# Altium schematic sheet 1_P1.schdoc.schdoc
size 309 x 223 mm; Symbol: Sheet-Symbol_A4; Device: Sheet-Symbol_A4; @Page Name: P1; @Create Date: 2023-11-13; @Page Count: 1; @Page No: 1; @Project Name: circuller; @Schematic Name: Ver 2; @Update Date: 2023-11-14; Company: MPAM Laboratory; Drawed: FDS; Page Size: A4; Part Number: M-CIR-PCB-1; Reviewed: FDS; Version: V1.0
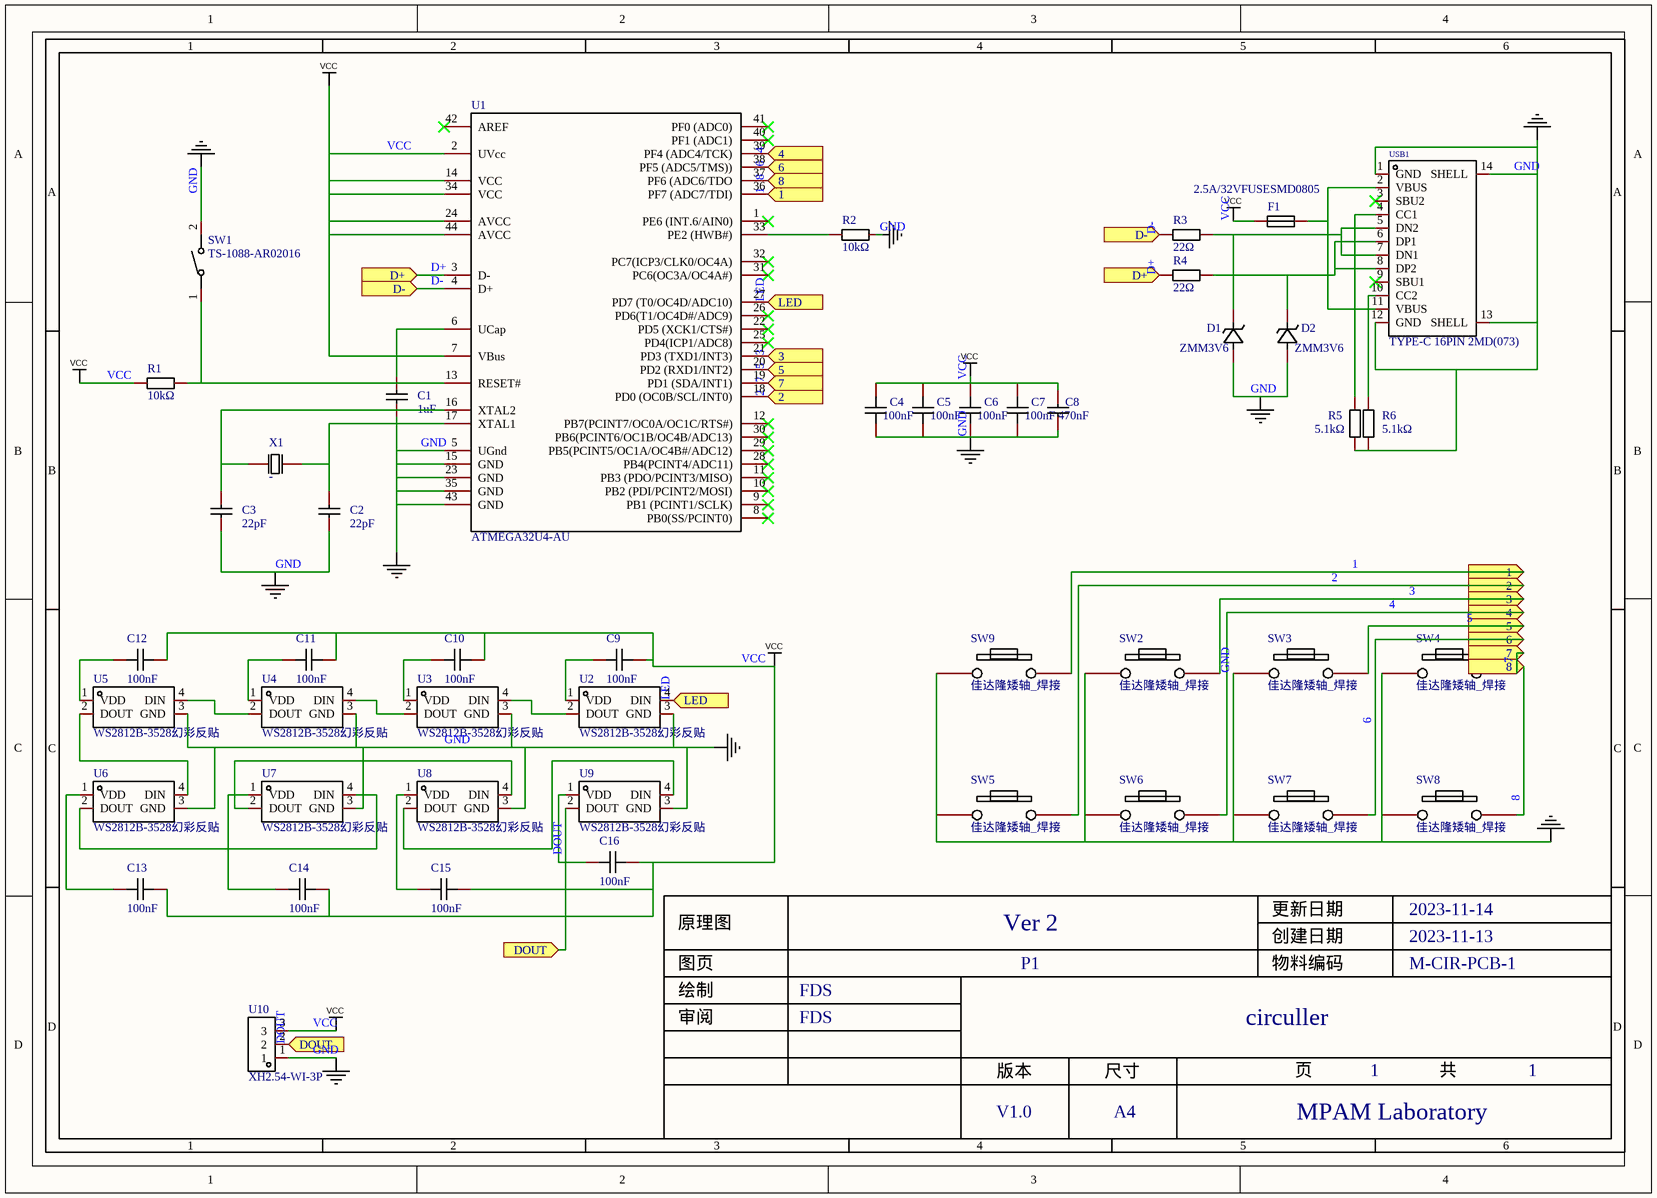
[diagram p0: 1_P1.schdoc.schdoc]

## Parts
C1  1uF  [C0603]
C2  22pF  [C0603]
C3  22pF  [C0603]
C4  100nF  [C0603]
C5  100nF  [C0603]
C6  100nF  [C0603]
C7  100nF  [C0603]
C8  470nF  [C0603]
C9  100nF  [C0603]
C10  100nF  [C0603]
C11  100nF  [C0603]
C12  100nF  [C0603]
C13  100nF  [C0603]
C14  100nF  [C0603]
C15  100nF  [C0603]
C16  100nF  [C0603]
D1  ZMM3V6  [LL-34_L3.5-W1.5-RD]
D2  ZMM3V6  [LL-34_L3.5-W1.5-RD]
F1  2.5A/32VFUSESMD0805  [F0805]
R1  10kΩ  [R0603]
R2  10kΩ  [R0603]
R3  22Ω  [R0603]
R4  22Ω  [R0603]
R5  5.1kΩ  [R0603]
R6  5.1kΩ  [R0603]
SW1  TS-1088-AR02016  [SW-SMD_L3.9-W3.0-P4.45]
SW2  佳达隆矮轴_焊接  [佳达隆矮轴焊接]
SW3  佳达隆矮轴_焊接  [佳达隆矮轴焊接]
SW4  佳达隆矮轴_焊接  [佳达隆矮轴焊接]
SW5  佳达隆矮轴_焊接  [佳达隆矮轴焊接]
SW6  佳达隆矮轴_焊接  [佳达隆矮轴焊接]
SW7  佳达隆矮轴_焊接  [佳达隆矮轴焊接]
SW8  佳达隆矮轴_焊接  [佳达隆矮轴焊接]
SW9  佳达隆矮轴_焊接  [佳达隆矮轴焊接]
U1  ATMEGA32U4-AU  [QFP-44_L10.0-W10.0-P0.80-LS13.2-BL]
U2  WS2812B-3528幻彩反贴  [LED-SMD_L3.2-W2.8-TR]
U3  WS2812B-3528幻彩反贴  [LED-SMD_L3.2-W2.8-TR]
U4  WS2812B-3528幻彩反贴  [LED-SMD_L3.2-W2.8-TR]
U5  WS2812B-3528幻彩反贴  [LED-SMD_L3.2-W2.8-TR]
U6  WS2812B-3528幻彩反贴  [LED-SMD_L3.2-W2.8-TR]
U7  WS2812B-3528幻彩反贴  [LED-SMD_L3.2-W2.8-TR]
U8  WS2812B-3528幻彩反贴  [LED-SMD_L3.2-W2.8-TR]
U9  WS2812B-3528幻彩反贴  [LED-SMD_L3.2-W2.8-TR]
U10  XH2.54-WI-3P  [CONN-TH_XH2.54-WI-3P]
USB1  TYPE-C 16PIN 2MD(073)  [USB-C-SMD_TYPE-C-6PIN-2MD-073]
X1  -  [OSC-SMD_2P-L5.0-W3.2]

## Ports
1 (in), 2 (in), 3 (in), 4 (in), 5 (in), 6 (in), 7 (in), 8 (in), D+ (in), D- (in), DOUT (in), LED (in)

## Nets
GND: C1.1 C2.1 C3.1 C4.1 C5.1 C6.1 C7.1 C8.1 D1.2(A) D2.2(A) R2.2 R5.1 R6.1 SW1.2 SW2.1 SW3.1 SW4.1 SW5.1 SW6.1 SW7.1 SW8.1 SW9.1 U1.5(UGnd) U1.15(GND) U1.23(GND) U1.35(GND) U1.43(GND) U2.3(GND) U3.3(GND) U4.3(GND) U5.3(GND) U6.3(GND) U7.3(GND) U8.3(GND) U9.3(GND) U10.1 USB1.1(GND) USB1.12(GND) USB1.13(SHELL) USB1.14(SHELL)
VCC: C4.2 C5.2 C6.2 C7.2 C8.2 C9.2 C10.2 C11.2 C12.2 C13.2 C14.2 C15.2 C16.2 F1.1 R1.1 U1.2(UVcc) U1.7(VBus) U1.14(VCC) U1.24(AVCC) U1.34(VCC) U1.44(AVCC) U10.3
1: SW9.2 U1.36(PF7_(ADC7/TDI)) ; port 1
2: SW5.2 U1.18(PD0_(OC0B/SCL/INT0)) ; port 2
3: SW2.2 U1.21(PD3_(TXD1/INT3)) ; port 3
4: SW6.2 U1.39(PF4_(ADC4/TCK)) ; port 4
5: SW3.2 U1.20(PD2_(RXD1/INT2)) ; port 5
6: SW7.2 U1.38(PF5_(ADC5/TMS))) ; port 6
7: SW4.2 U1.19(PD1_(SDA/INT1)) ; port 7
8: SW8.2 U1.37(PF6_(ADC6/TDO) ; port 8
D+: R4.1 U1.3(D-) ; port D+
D-: R3.1 U1.4(D+) ; port D-
DOUT: U9.2(DOUT) U10.2 ; port DOUT
LED: U1.27(PD7_(T0/OC4D/ADC10)) U2.4(DIN) ; port LED
NetC1_2: C1.2 U1.6(UCap)
NetC2_2: C2.2 U1.17(XTAL1) X1.2(OSC2)
NetC3_2: C3.2 U1.16(XTAL2) X1.1(OSC1)
NetC9_1: C9.1 U2.1(VDD)
NetC10_1: C10.1 U3.1(VDD)
NetC11_1: C11.1 U4.1(VDD)
NetC12_1: C12.1 U5.1(VDD)
NetC13_1: C13.1 U6.1(VDD)
NetC14_1: C14.1 U7.1(VDD)
NetC15_1: C15.1 U8.1(VDD)
NetC16_1: C16.1 U9.1(VDD)
NetD1_1: D1.1(K) R3.2 USB1.5(DN2) USB1.7(DN1)
NetD2_1: D2.1(K) R4.2 USB1.6(DP1) USB1.8(DP2)
NetF1_2: F1.2 USB1.2(VBUS) USB1.11(VBUS)
NetR1_2: R1.2 SW1.1 U1.13(RESET#)
NetR2_1: R2.1 U1.33(PE2_(HWB#))
NetR5_2: R5.2 USB1.4(CC1)
NetR6_2: R6.2 USB1.10(CC2)
NetU2_2: U2.2(DOUT) U3.4(DIN)
NetU3_2: U3.2(DOUT) U4.4(DIN)
NetU4_2: U4.2(DOUT) U5.4(DIN)
NetU5_2: U5.2(DOUT) U6.4(DIN)
NetU6_2: U6.2(DOUT) U7.4(DIN)
NetU7_2: U7.2(DOUT) U8.4(DIN)
NetU8_2: U8.2(DOUT) U9.4(DIN)

Not connected (* = marked no-connect by the designer): U1 1(PE6_(INT.6/AIN0))* 8(PB0(SS/PCINT0))* 9(PB1_(PCINT1/SCLK))* 10(PB2_(PDI/PCINT2/MOSI))* 11(PB3_(PDO/PCINT3/MISO))* 12(PB7(PCINT7/OC0A/OC1C/RTS#))* 22(PD5_(XCK1/CTS#))* 25(PD4(ICP1/ADC8))* 26(PD6(T1/OC4D#/ADC9))* 28(PB4(PCINT4/ADC11))* 29(PB5(PCINT5/OC1A/OC4B#/ADC12))* 30(PB6(PCINT6/OC1B/OC4B/ADC13))* 31(PC6(OC3A/OC4A#))* 32(PC7(ICP3/CLK0/OC4A))* 40(PF1_(ADC1))* 41(PF0_(ADC0))* 42(AREF)*; USB1 3(SBU2)* 9(SBU1)*

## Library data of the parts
C1 = CL10A105KB8NNNC: 容值:1uF;精度:±10%;额定电压:50V;材质(温度系数):X5R;; Manufacturer: SAMSUNG(三星); Add into BOM: yes; Tolerance: ±10%; Voltage Rated: 50V; Temperature Coefficient: X5R
C2 C3 = CL10C220JB8NNNC: 容值:22pF;精度:±5%;额定电压:50V;材质(温度系数):C0G;; Manufacturer: SAMSUNG(三星); Add into BOM: yes; Tolerance: ±5%; Voltage Rated: 50V; Temperature Coefficient: C0G
C4-C7 = CC0603KRX7R9BB104: 容值:100nF;精度:±10%;额定电压:50V;材质(温度系数):X7R;; Manufacturer: YAGEO(国巨); Add into BOM: yes; Tolerance: ±10%; Voltage Rated: 50V; Temperature Coefficient: X7R
C8 = CL10B474KA8NNNC: 容值:470nF;精度:±10%;额定电压:25V;材质(温度系数):X7R;; Manufacturer: SAMSUNG(三星); Add into BOM: yes; Tolerance: ±10%; Voltage Rated: 25V; Temperature Coefficient: X7R
C9-C16 = CC0603KRX7R9BB104: 容值:100nF;精度:±10%;额定电压:50V;材质(温度系数):X7R;; Manufacturer: YAGEO(国巨); Symbol: CapAcitance; Add into BOM: yes; Tolerance: ±10%; Voltage Rated: 50V; Temperature Coefficient: X7R; Check: true
D1 D2 = ZMM3V6: 稳压值(标称值):-;精度:-;功率:500mW;反向电流(Ir):2uA@1V;; Manufacturer: Slkor(萨科微); Symbol: ZMM3V6_C707190; Add into BOM: yes; Power Dissipation: 500mW; Reverse Leakage Current (Ir): 2uA@1V
F1 = 2.5A/32VFUSESMD0805: Add into BOM: yes
R1 R2 = 0603WAF1002T5E: 电阻类型:厚膜电阻;阻值:10kΩ;精度:±1%;功率:100mW;; Manufacturer: UNI-ROYAL(厚声); Add into BOM: yes; Tolerance: ±1%; Power(Watts): 100mW; Temperature Coefficient: ±100ppm/℃; Overload Voltage (Max): 75V
R3 R4 = 0603WAF220JT5E: 电阻类型:厚膜电阻;阻值:22Ω;精度:±1%;功率:100mW;温度系数:±100ppm/℃;; Manufacturer: UNI-ROYAL(厚声); Add into BOM: yes; Tolerance: ±1%; Power(Watts): 100mW; Overload Voltage (Max): 75V
R5 R6 = 0603WAF5101T5E: 电阻类型:厚膜电阻;阻值:5.1kΩ;精度:±1%;功率:100mW;温度系数:±100ppm/℃;; Manufacturer: UNI-ROYAL(厚声); Add into BOM: yes; Tolerance: ±1%; Power(Watts): 100mW; Overload Voltage (Max): 75V
SW1 = TS-1088-AR02016: 触点电流:50mA;额定电压(DC):12V;绝缘电阻:100MΩ;电路结构:单刀单掷;安装方式:立贴;作用力:160gf@±50gf;机械寿命:10万次;带支架:否;; Manufacturer: XUNPU(讯普); Add into BOM: yes; Contact Current: 50mA; Voltage Rating (DC): 12V; Insulation Resistance: 100MΩ; Circuit: 单刀单掷; Actuator Style: 圆形按钮; Actuator/Cap Color: 黑色; Mechanical Life: 10万次; Pin Style: SMD接片; Switch Length: 4mm; Switch Width: 3mm; Switch Height: 2mm; Strike Gundam: 否
SW2-SW9 = 佳达隆矮轴_焊接: Add into BOM: yes
U1 = ATMEGA32U4-AU: CPU内核:AVR;CPU最大主频:16MHz;工作电压范围:2.7V~5.5V;程序存储容量:32KB;程序存储器类型:FLASH;RAM总容量:2.5KB;GPIO端口数量:26;; Manufacturer: MICROCHIP(美国微芯); Add into BOM: yes; CPU Core: AVR; CPU Maximum Speed: 16MHz; Program Storage Size: 32KB; Program Memory Type: FLASH; RAM Size: 2.5KB; EEPROM: 1KB; GPIO Ports Number: 26; ADC (Bit): 10bit; Universal Serial Bus: 有; Peripheral/Function: 看门狗；PWM
U2-U9 = WS2812B-3528幻彩反贴: Add into BOM: yes
U10 = XH2.54-WI-3P: Add into BOM: yes
USB1 = TYPE-C 16PIN 2MD(073): 连接器类型:Type-C;标准:-;公母:母座;触点数量:16;端口数量:1;安装方式:卧贴;额定电流 - 电源:5A;工作温度范围:-25℃~+85℃;; Manufacturer: SHOU HAN(首韩); Add into BOM: yes; Gender: 母座; Number of Contacts: 16; Number of Ports: 1; Current Rating - Power (Max): 5A
X1 = XSHEELNANF-16MHZ: 频率:-;负载电容:-;; Manufacturer: TAITIEN(泰艺电子); Add into BOM: yes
